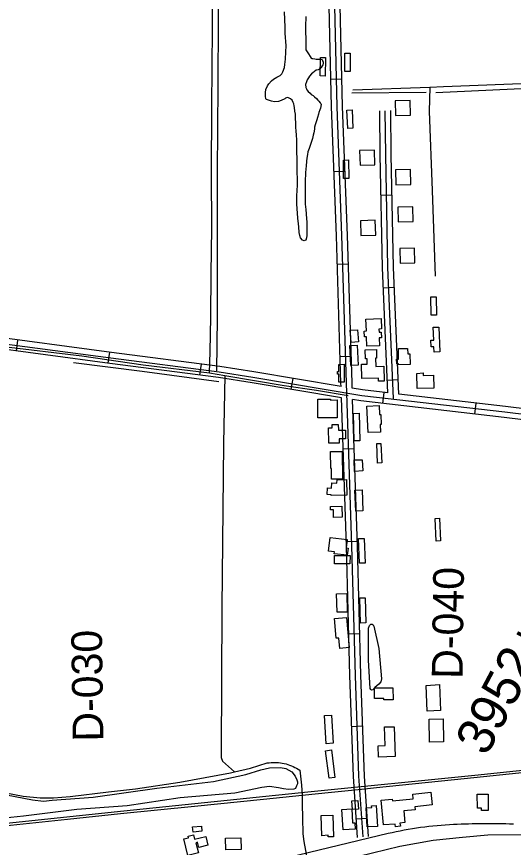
# Model space of a CAD drawing. Extents: x 3445503 to 3483459, y 540493 to 566012.
# Drawn here: x 3463733 to 3465075, y 553510 to 555755 of the extents above; entities that cross this region are included whole.
import ezdxf

# ---------------------------------------------------------------- set-up
doc = ezdxf.new("R2010")
doc.units = 0
for name, color, linetype in [('V-BLDG-OTLN', 7, 'Continuous'), ('V-DTCH-CNTR', 7, 'Continuous'), ('V-LEVE-TOET', 7, 'Continuous'), ('V-RAIL-TRAK', 7, 'Continuous'), ('V-RIVR-RANG-IDEN', 7, 'Continuous'), ('V-ROAD-CNTR', 7, 'Continuous'), ('V-SITE-VEGE', 7, 'Continuous'), ('V-SURV-IDEN', 7, 'Continuous'), ('V-TOPO-SHOR', 7, 'Continuous')]:
    doc.layers.add(name, color=color, linetype=linetype)

msp = doc.modelspace()

# ---------------------------------------------------------------- linework, layer by layer
at = {"layer": 'V-BLDG-OTLN'}
for points in [[(3464552.9878560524, 555594.4947846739), (3464554.1908536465, 555644.4806847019), (3464568.186825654, 555644.1436853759), (3464566.9838280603, 555594.1587853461)], [(3464634.2806934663, 555656.328661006), (3464634.32869337, 555606.3287610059), (3464620.3287213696, 555606.314761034), (3464620.280721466, 555656.3146610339)], [(3464756.330449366, 555527.7119182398), (3464757.1204477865, 555487.719998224), (3464797.1123678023, 555488.509996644), (3464796.322369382, 555528.5019166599)], [(3464639.6536827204, 555503.1039674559), (3464641.797678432, 555453.150067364), (3464627.8107064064, 555452.5500685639), (3464625.6657106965, 555502.5039686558)], [(3464701.0565599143, 555354.3532649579), (3464699.7665624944, 555394.3331849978), (3464659.7876424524, 555393.0441875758), (3464661.076639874, 555353.0642675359)], [(3464630.0230366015, 555367.5500286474), (3464630.818035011, 555317.5571286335), (3464616.8200630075, 555317.3341290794), (3464616.025064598, 555367.3280290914)], [(3464757.2384475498, 555340.6522923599), (3464758.0284459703, 555300.6603723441), (3464798.020365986, 555301.450370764), (3464797.230367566, 555341.4422907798)], [(3464763.505435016, 555240.275493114), (3464764.2954334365, 555200.2835730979), (3464804.287353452, 555201.073571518), (3464803.4973550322, 555241.065491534)], [(3464703.4295551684, 555164.68764429), (3464702.139557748, 555204.6675643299), (3464662.160637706, 555203.378566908), (3464663.449635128, 555163.398646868)], [(3464768.481425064, 555128.6677163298), (3464769.2714234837, 555088.675796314), (3464809.2633435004, 555089.465794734), (3464808.4733450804, 555129.4577147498)], [(3464866.7916951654, 554998.0646418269), (3464867.2241945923, 554948.0668042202), (3464853.224880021, 554947.9457069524), (3464852.792348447, 554997.9445440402)], [(3464679.497, 554864.221), (3464678.555, 554890.001), (3464672.757, 554889.7880000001), (3464672.19, 554905.269), (3464678.311, 554905.495), (3464677.144, 554937.378), (3464718.073, 554938.875), (3464719.095, 554910.95), (3464712.12, 554910.705), (3464712.429, 554901.935), (3464718.171, 554902.138), (3464718.7060000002, 554886.9890000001), (3464712.449, 554886.768), (3464713.207, 554865.317)], [(3464654.018, 554908.562), (3464656.715, 554875.639), (3464636.896, 554874.015), (3464634.543, 554907.422)], [(3464873.93, 554915.405), (3464876.396, 554848.904), (3464861.011, 554848.333), (3464860.468, 554862.943), (3464853.0100000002, 554862.667), (3464852.348, 554880.519), (3464860.04, 554880.804), (3464858.764, 554915.245)], [(3464653.727, 554867.3960000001), (3464656.053, 554812.806), (3464636.028, 554811.956), (3464633.896, 554866.279)], [(3464725.4990000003, 554810.183), (3464725.8370000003, 554769.446), (3464710.848, 554769.321), (3464710.778, 554777.642), (3464665.544, 554777.259), (3464665.222, 554815.383), (3464680.203, 554815.512), (3464680.0810000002, 554830.188), (3464675.382, 554830.147), (3464675.159, 554854.854), (3464705.65, 554855.1240000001), (3464705.855, 554831.977), (3464703.112, 554831.955), (3464703.323, 554809.6730000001)], [(3464795.823, 554843.975), (3464796.774, 554815.157), (3464765.019, 554814.115), (3464764.946, 554816.333), (3464760.17, 554816.177), (3464759.77, 554829.034), (3464765.1380000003, 554829.219), (3464764.737, 554857.95), (3464789.538, 554858.229), (3464790.1950000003, 554843.696)], [(3464618.231, 554815.536), (3464618.3680000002, 554767.441), (3464603.42, 554767.404), (3464603.365, 554788.8420000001), (3464600.106, 554788.836), (3464600.09, 554795.986), (3464603.553, 554795.9940000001), (3464603.723, 554815.061)], [(3464814.378, 554790.868), (3464831.68, 554791.888), (3464831.858, 554785.213), (3464859.2970000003, 554785.9450000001), (3464860.221, 554751.186), (3464815.472, 554749.9940000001)], [(3464599.303, 554718.938), (3464599.228, 554670.622), (3464547.333, 554670.72), (3464547.395, 554721.306), (3464581.091, 554721.248), (3464581.095, 554718.678)], [(3464682.7630000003, 554631.431), (3464679.739, 554702.274), (3464713.076, 554703.687), (3464714.096, 554679.975), (3464717.063, 554680.03), (3464718.044, 554652.509), (3464715.1920000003, 554652.435), (3464715.97, 554631.716)], [(3464643.397, 554682.017), (3464658.5640000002, 554682.902), (3464660.6720000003, 554608.803), (3464645.562, 554608.354)], [(3464604.268, 554602.1410000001), (3464576.755, 554601.844), (3464576.274, 554643.578), (3464585.733, 554643.674), (3464585.69, 554652.765), (3464602.386, 554652.837), (3464602.472, 554637.231), (3464622.149, 554637.264), (3464622.126, 554613.458), (3464604.235, 554613.566)], [(3464613.58, 554505.125), (3464583.5870000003, 554505.029), (3464583.6010000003, 554533.563), (3464581.795, 554533.432), (3464581.451, 554579.443), (3464612.929, 554579.658)], [(3464717.485, 554601.033), (3464719.589, 554548.807), (3464708.662, 554548.366), (3464706.541, 554601.252)], [(3464667.113, 554557.105), (3464668.501, 554526.981), (3464646.432, 554525.965), (3464645.017, 554556.685)], [(3464624.848, 554503.638), (3464625.841, 554461.609), (3464583.159, 554460.6730000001), (3464583.126, 554462.774), (3464572.294, 554463.102), (3464572.9390000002, 554481.126), (3464583.7060000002, 554480.9130000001), (3464584.791, 554495.071), (3464598.597, 554494.41), (3464599.129, 554502.9890000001)], [(3464647.413, 554474.903), (3464666.414, 554475.875), (3464668.563, 554419.203), (3464649.311, 554418.554)], [(3464581.295, 554431.36), (3464612.06, 554432.316), (3464612.98, 554402.26), (3464589.586, 554401.549), (3464588.971, 554422.214), (3464581.035, 554422.064)], [(3464866.944, 554337.263), (3464864.38, 554398.594), (3464875.857, 554399.073), (3464878.409, 554337.9940000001)], [(3464626.216, 554299.389), (3464591.097, 554303.403), (3464591.681, 554308.433), (3464576.108, 554310.325), (3464580.748, 554347.656), (3464626.075, 554342.008), (3464623.29, 554319.201), (3464629.327, 554318.235)], [(3464672.028, 554344.814), (3464674.819, 554278.292), (3464660.012, 554277.67), (3464657.196, 554344.449)], [(3464633.867, 554276.224), (3464592.043, 554276.316), (3464592.094, 554298.287), (3464634.2460000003, 554298.191)], [(3464625.024, 554196.078), (3464626.04, 554145.805), (3464598.8710000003, 554145.261), (3464597.876, 554195.049)], [(3464674.686, 554184.089), (3464676.617, 554116.478), (3464662.359, 554116.074), (3464660.4220000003, 554183.863)], [(3464624.35, 554130.63), (3464631.305, 554049.603), (3464606.045, 554047.434), (3464603.631, 554075.573), (3464596.926, 554074.998), (3464592.4590000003, 554127.867)], [(3464700.44, 553940.555), (3464750.083, 553940.7), (3464750.177, 553908.831), (3464725.0300000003, 553908.76), (3464725.022, 553911.795), (3464699.875, 553911.723)], [(3464875.361, 553949.955), (3464878.169, 553879.508), (3464842.512, 553878.074), (3464839.759, 553947.35)], [(3464584.382, 553867.214), (3464588.072, 553790.944), (3464569.171, 553790.029), (3464565.481, 553866.2980000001)], [(3464885.3910000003, 553856.765), (3464886.4390000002, 553794.7660000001), (3464848.795, 553794.143), (3464847.728, 553855.833)], [(3464753.211, 553835.781), (3464756.264, 553755.362), (3464711.012, 553753.642), (3464709.863, 553783.9130000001), (3464728.995, 553784.6410000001), (3464727.307, 553835.486)], [(3464583.575, 553773.161), (3464593.327, 553698.643), (3464577.504, 553696.5700000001), (3464567.8170000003, 553770.567)], [(3464724.457, 553570.833), (3464718.098, 553637.002), (3464748.326, 553639.984), (3464748.8200000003, 553635.104), (3464804.468, 553640.691), (3464803.477, 553653.984), (3464852.166, 553658.926), (3464855.916, 553624.737), (3464809.262, 553619.238), (3464809.934, 553610.921), (3464779.392, 553608.121), (3464782.239, 553577.151), (3464768.896, 553575.003), (3464769.994, 553566.782), (3464757.2430000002, 553565.089), (3464756.156, 553572.767)], [(3464640.603, 553611.824), (3464639.235, 553635.833), (3464655.4250000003, 553636.754), (3464656.801, 553612.602)], [(3465007.574, 553653.5480000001), (3465007.052, 553609.528), (3464989.103, 553609.735), (3464989.21, 553615.754), (3464978.196, 553615.517), (3464977.653, 553653.245)], [(3464612.048, 553612.393), (3464639.088, 553614.337), (3464640.89, 553575.898), (3464647.2120000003, 553576.189), (3464648.181, 553558.756), (3464615.132, 553556.919)], [(3464704.812, 553622.7220000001), (3464707.897, 553566.6), (3464680.146, 553565.111), (3464677.33, 553616.393), (3464692.514, 553617.2170000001), (3464692.186, 553622.326)], [(3464587.435, 553597.068), (3464589.2290000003, 553538.674), (3464574.705, 553538.235), (3464574.707, 553542.491), (3464558.075, 553541.178), (3464555.968, 553596.003)], [(3464208.6920000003, 553564.882), (3464232.31, 553567.213), (3464233.662, 553553.444), (3464210.38, 553551.158)], [(3464184.745, 553532.833), (3464197.918, 553535.931), (3464196.796, 553540.242), (3464211.0500000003, 553543.671), (3464214.001, 553531.561), (3464244.088, 553539.022), (3464249.788, 553515.754), (3464225.631, 553509.7660000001), (3464222.275, 553523.375), (3464217.751, 553522.261), (3464224.56, 553494.783), (3464195.927, 553487.691)], [(3464339.605, 553504.103), (3464298.188, 553503.335), (3464297.602, 553534.838), (3464338.595, 553535.598)]]:
    msp.add_lwpolyline(points, close=True, dxfattribs=at)
at = {"layer": 'V-DTCH-CNTR'}
for points in [[(3464254.058, 554791.97), (3464256.487, 554849.428), (3464257.832, 554943.561), (3464259.114, 555060.09), (3464260.376, 555183.435), (3464259.296, 555330.4670000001), (3464260.39, 555510.937), (3464262.688, 555723.8690000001), (3464263.458, 555903.366), (3464259.055, 555966.322)], [(3466325.821, 555717.35), (3466190.882, 555693.9130000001), (3465990.727, 555666.064), (3465767.855, 555637.827), (3465492.426, 555603.9180000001), (3465341.574, 555584.327), (3465142.988, 555574.984), (3464886.9590000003, 555564.822), (3464849.546, 555563.525), (3464641.312, 555556.312)], [(3464849.546, 555563.525), (3464847.787, 555499.263), (3464855.555, 555285.093), (3464864.345, 555053.727)], [(3462920.117, 555016.9180000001), (3462976.88, 555005.416), (3463146.526, 554968.634), (3463259.1, 554937.519), (3463342.157, 554913.127), (3463386.269, 554904.503), (3463527.014, 554884.8200000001), (3463697.585, 554863.275), (3463909.664, 554837.964), (3464075.38, 554814.137), (3464254.058, 554791.97)], [(3464254.058, 554791.97), (3464295.395, 554785.062), (3464456.109, 554758.2), (3464543.346, 554745.814), (3464628.666, 554731.134)], [(3464295.395, 554785.062), (3464292.126, 554601.145), (3464288.097, 554157.172), (3464285.818, 553765.746), (3464285.474, 553752.7980000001), (3464289.693, 553742.9130000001), (3464321.64, 553713.853)], [(3463633.77, 553670.247), (3463638.292, 553669.291), (3463679.794, 553661.31), (3463751.126, 553648.231), (3463796.8310000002, 553643.507), (3463832.803, 553643.935), (3463877.836, 553647.308), (3463981.174, 553660.2490000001), (3464054.0640000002, 553667.917), (3464173.911, 553686.414), (3464310.914, 553711.4450000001), (3464321.64, 553713.853), (3464364.998, 553723.594), (3464410.324, 553737.985)], [(3464410.324, 553737.985), (3464415.401, 553738.653), (3464420.503, 553739.107), (3464425.617, 553739.351), (3464430.739, 553739.384), (3464435.859, 553739.204), (3464440.964, 553738.81), (3464446.052, 553738.204), (3464451.108, 553737.389), (3464456.13, 553736.365), (3464461.102, 553735.134), (3464466.02, 553733.699), (3464470.873, 553732.058), (3464475.6550000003, 553730.221), (3464480.358, 553728.185), (3464484.972, 553725.955), (3464489.488, 553723.5380000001), (3464493.901, 553720.935), (3464498.202, 553718.15)], [(3464498.202, 553718.15), (3464502.857, 553678.304), (3464504.428, 553651.115), (3464504.4990000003, 553626.488), (3464505.257, 553589.2220000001), (3464506.678, 553546.45), (3464509.654, 553525.718), (3464516.753, 553487.085)]]:
    msp.add_lwpolyline(points, dxfattribs=at)
at = {"layer": 'V-LEVE-TOET'}
msp.add_lwpolyline([(3464658.224, 553486.218), (3464768.751, 553512.568), (3464858.486, 553529.095), (3464937.8340000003, 553537.787), (3465006.128, 553543.843), (3465102.417, 553544.775), (3465298.912, 553540.795), (3465626.836, 553534.6), (3465949.56, 553526.439), (3466237.791, 553522.079), (3466528.632, 553515.775), (3466792.791, 553511.343), (3466823.378, 553508.181)], dxfattribs=at)
at = {"layer": 'V-RAIL-TRAK'}
msp.add_lwpolyline([(3463647.612, 553562.609), (3463870.883, 553585.628), (3464013.461, 553600.957), (3464213.722, 553621.317), (3464400.375, 553640.017), (3464504.428, 553651.115), (3464583.788, 553659.031), (3464665.257, 553667.505), (3464705.627, 553671.706), (3464942.184, 553695.737), (3465116.522, 553713.751), (3465289.563, 553731.438), (3465488.203, 553752.765), (3465635.966, 553768.109), (3465761.699, 553780.796), (3465957.099, 553800.818)], dxfattribs=at)
at = {"layer": 'V-ROAD-CNTR'}
for p, q in [((3464582.247797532, 555586.1208014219), (3464612.239737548, 555586.8048000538)), ((3464590.584780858, 555336.040301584), (3464620.5627209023, 555337.1752993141)), ((3464717.6675266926, 555272.693428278), (3464747.661466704, 555273.256427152)), ((3464599.5217629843, 555086.3038010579), (3464629.507703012, 555087.2357991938)), ((3464723.664514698, 555022.4169288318), (3464753.636454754, 555023.7019262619)), ((3463732.8304963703, 554851.1762713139), (3463736.7704884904, 554880.916211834)), ((3463980.666000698, 554818.3503369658), (3463984.60499282, 554848.0902774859)), ((3464607.2917474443, 554836.424300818), (3464637.2766874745, 554837.3572989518)), ((3464228.6195047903, 554786.1334013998), (3464232.4834970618, 554815.8833418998)), ((3464475.0690118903, 554747.671478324), (3464480.0090020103, 554777.2624191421)), ((3464734.377493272, 554772.6464283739), (3464764.350433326, 554773.932425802)), ((3464722.829516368, 554709.3835549), (3464726.2635095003, 554739.1864952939)), ((3464971.185019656, 554680.76361214), (3464974.620012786, 554710.5665525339)), ((3464615.5147309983, 554586.522800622), (3464645.497671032, 554587.5307986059)), ((3464623.91871419, 554336.66430034), (3464653.9016542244, 554337.6722983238)), ((3464630.5467009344, 554086.8647999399), (3464660.536640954, 554087.6497983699)), ((3464638.335685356, 553836.853299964), (3464668.316625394, 553837.9102978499)), ((3464650.877660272, 553586.7138002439), (3464680.80860041, 553588.742796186))]:
    msp.add_line(p, q, dxfattribs=at)
for points in [[(3464640.014681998, 554750.5524725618), (3464639.513683, 554765.420442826), (3464627.134707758, 555163.5386465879), (3464613.949734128, 555511.922949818), (3464603.285755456, 555979.0970154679), (3464587.05378792, 556403.0031676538), (3464588.709784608, 556520.0239336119), (3464579.83880235, 556696.1285814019), (3464566.4518291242, 557015.8579419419), (3464565.69383064, 557133.317707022), (3464478.852004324, 557129.8217140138)], [(3464609.827742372, 554755.5914624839), (3464609.5297429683, 554764.4504447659), (3464597.152767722, 555162.5046486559), (3464583.961794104, 555511.012951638), (3464573.299815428, 555978.1810172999), (3464557.045847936, 556402.641168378), (3464558.6998446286, 556519.481934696), (3464549.870862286, 556694.7465841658), (3464536.4558891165, 557015.1339433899), (3464535.8938902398, 557102.09376947), (3464480.058001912, 557099.8457739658)], [(3464669.224623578, 553537.842897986), (3464658.105645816, 553701.8675699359), (3464648.490665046, 553974.4790247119), (3464639.3396833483, 554324.4073248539), (3464624.521712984, 554764.935443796), (3464612.14373774, 555163.0216476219), (3464598.9557641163, 555511.4679507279), (3464588.2927854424, 555978.6390163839)], [(3464735.860490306, 554738.081497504), (3464721.3525193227, 555076.305821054), (3464715.6185307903, 555381.8822099), (3464714.1345337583, 555500.500972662)], [(3464751.506459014, 554723.335526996), (3464736.346489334, 555076.7678201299), (3464730.6165007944, 555382.11720943), (3464729.13350376, 555500.688972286)], [(3464766.036429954, 554734.6035044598), (3464751.340459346, 555077.229819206), (3464745.614470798, 555382.3522089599), (3464744.132473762, 555500.87697191)], [(3464609.827742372, 554755.5914624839), (3464374.047213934, 554794.950383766), (3464282.6873966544, 554809.36335494), (3463989.2509835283, 554847.4752787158), (3463639.962682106, 554893.7381861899), (3463418.709124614, 554912.3141490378), (3463332.4262971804, 554940.2690931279), (3463277.285407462, 554958.12305742), (3463208.6945446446, 554982.512008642), (3463157.18164767, 554995.07298352), (3462918.576124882, 555036.0539015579), (3462796.2523695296, 555038.326897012)], [(3464610.856740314, 554725.0045236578), (3464369.23922355, 554765.3384429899), (3464278.417405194, 554779.665414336), (3463985.348991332, 554817.729338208), (3463636.736688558, 554863.904245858), (3463412.7531365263, 554882.7082082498), (3463323.182315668, 554911.7291502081), (3463267.6374267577, 554929.71311424), (3463200.0925618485, 554953.730066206), (3463151.08165987, 554965.6810423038), (3462915.7421305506, 555006.1019614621), (3462795.694370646, 555008.332957)], [(3463638.3496853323, 554878.8212160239), (3463987.29998743, 554832.6023084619), (3464280.552400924, 554794.5143846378), (3464371.643218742, 554780.144413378), (3464665.5096310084, 554731.0885114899), (3465052.138857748, 554686.5336006), (3465440.0010820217, 554638.8926958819), (3465471.7460185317, 554638.096697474), (3465512.085937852, 554636.930699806), (3465552.17185768, 554636.9556997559), (3465650.6256607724, 554644.390684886), (3466146.099669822, 554711.1975512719), (3466532.7968964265, 554756.6004604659), (3466917.007128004, 554810.084353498), (3467040.951880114, 554820.7023322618), (3467493.343975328, 554879.0952154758), (3467696.094569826, 554903.5841664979), (3467752.335457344, 554909.2991550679)], [(3466439.5670828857, 554760.757452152), (3466144.2226735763, 554726.0805215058), (3465649.057663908, 554659.314655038), (3465551.60185882, 554651.9556697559), (3465512.297937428, 554651.930669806), (3465472.151017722, 554653.0916674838), (3465441.106079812, 554653.869665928), (3465053.9118542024, 554701.4285708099), (3464766.036429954, 554734.6035044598)], [(3464735.860490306, 554738.081497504), (3464667.604626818, 554745.9464817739), (3464640.014681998, 554750.5524725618)], [(3464654.2586535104, 553536.8289000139), (3464643.1236757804, 553701.0955714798), (3464633.497695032, 553974.019025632), (3464624.3467133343, 554323.9593257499), (3464610.856740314, 554725.0045236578)], [(3466444.176073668, 554731.092511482), (3466147.976666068, 554696.314581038), (3465652.193657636, 554629.4667147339), (3465552.7418565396, 554621.9557297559), (3465511.8739382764, 554621.930729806), (3465471.3410193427, 554623.101727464), (3465438.8960842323, 554623.9157258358), (3465050.365861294, 554671.6386303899), (3464663.414635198, 554716.2305412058), (3464641.042679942, 554719.965533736)], [(3464684.190593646, 553538.856895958), (3464673.0876158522, 553702.6395683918), (3464663.4836350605, 553974.939023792), (3464654.3326533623, 554324.855323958), (3464641.042679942, 554719.965533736)], [(3462633.1446957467, 553462.7350482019), (3463482.4409971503, 553551.6268704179), (3464022.895916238, 553608.7357561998), (3464520.2349215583, 553660.05565356), (3464971.126019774, 553704.8295640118), (3465529.4559031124, 553763.5944464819), (3465882.8481963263, 553800.9443717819), (3466138.079685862, 553826.5673205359), (3466333.4622950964, 553848.816276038), (3466574.421813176, 553870.9202318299), (3467118.44872512, 553928.552116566), (3467570.959820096, 553977.4020188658), (3467901.9681580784, 554011.130951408), (3468263.5194349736, 554044.7658841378), (3468297.7413665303, 554048.5228766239)], [(3464736.6394887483, 553546.798880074), (3464174.493613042, 553411.6311504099), (3463811.714338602, 553323.578326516), (3463601.09575984, 553279.424414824)]]:
    msp.add_lwpolyline(points, dxfattribs=at)
for centre, radius, start, end in [((3464963.076483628, 552568.1018587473), 1004.5504328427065, 92.80835923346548, 103.02706756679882), ((3465009.6029051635, 551301.8366162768), 2271.627840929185, 88.34062572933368, 92.41562850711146)]:
    msp.add_arc(centre, radius, start, end, dxfattribs=at)
at = {"layer": 'V-SITE-VEGE'}
for points in [[(3464440.731, 555525.934), (3464429.997, 555524.955), (3464421.785, 555526.512), (3464411.041, 555529.637), (3464407.881, 555530.89), (3464406.607, 555534.044), (3464405.644, 555539.408), (3464405.298, 555550.1410000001), (3464406.222, 555557.721), (3464410.613, 555567.838), (3464415.018, 555573.218), (3464422.254, 555581.765), (3464427.609, 555585.885), (3464436.117, 555591.593), (3464441.478, 555593.819), (3464445.261, 555596.039), (3464449.668, 555600.473), (3464452.495, 555605.534), (3464456.566, 555617.228), (3464458.1180000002, 555625.756), (3464459.654, 555640.284), (3464460.861, 555659.5480000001), (3464461.129, 555675.964), (3464458.819, 555710.057), (3464458.454, 555726.159), (3464456.754, 555768.145)], [(3464514.5670000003, 555755.685), (3464514.602, 555744.003), (3464513.984, 555739.581), (3464514.193, 555668.542), (3464514.8340000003, 555665.389), (3464521.4960000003, 555654.358), (3464526.569, 555646.795), (3464529.106, 555642.6950000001), (3464531.007, 555641.757), (3464533.532, 555641.447), (3464538.9020000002, 555640.5160000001), (3464542.691, 555640.21), (3464555.003, 555640.247), (3464559.111, 555639), (3464560.066, 555636.7880000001), (3464561.028, 555631.742)], [(3464561.028, 555631.742), (3464561.036, 555628.584), (3464560.416, 555625.108), (3464559.161, 555622.264), (3464556.3340000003, 555617.519), (3464555.077, 555615.618), (3464550.981, 555612.452), (3464548.142, 555611.495), (3464542.781, 555609.902), (3464533.327, 555602.929), (3464529.864, 555600.076), (3464524.83, 555594.063), (3464521.684, 555589.948), (3464518.2290000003, 555583.9400000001), (3464516.036, 555578.879), (3464514.162, 555571.615), (3464514.184, 555563.7220000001), (3464516.089, 555559.6240000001), (3464517.676, 555557.103), (3464520.529, 555553.007), (3464525.913, 555547.653), (3464529.393, 555544.507), (3464534.4560000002, 555541.368), (3464538.255, 555538.218), (3464543.3170000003, 555533.813), (3464547.438, 555529.088), (3464549.656, 555526.254), (3464553.772, 555522.16), (3464555.042, 555519.956), (3464555.9960000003, 555517.746), (3464554.131, 555507.637), (3464552.2490000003, 555503.214), (3464549.744, 555496.261), (3464548.497, 555490.889), (3464545.994, 555482.672), (3464544.433, 555476.354), (3464539.424, 555462.446), (3464538.179, 555456.128), (3464537.88, 555450.76), (3464536.012, 555440.969), (3464534.1380000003, 555434.331), (3464532.5840000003, 555425.803), (3464531.021, 555420.431), (3464528.83, 555414.742), (3464523.507, 555398.9400000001), (3464520.38, 555389.142), (3464519.134, 555382.509), (3464516.953, 555372.715), (3464516.032, 555364.187), (3464515.122, 555351.24), (3464514.83, 555343.662), (3464513.597, 555332.922), (3464513.6210000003, 555325.3470000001), (3464513.015, 555316.504), (3464513.1580000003, 555266.936), (3464512.878, 555255.567), (3464513.216, 555247.676), (3464514.203, 555234.102), (3464516.484, 555209.799), (3464517.146, 555199.698), (3464517.504, 555184.5430000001), (3464517.5330000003, 555175.386), (3464517.252, 555163.074), (3464516.64, 555157.073), (3464514.447, 555151.066), (3464512.241, 555149.483), (3464509.718, 555148.8420000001), (3464505.923, 555150.726), (3464500.537, 555157.341), (3464497.995, 555163.0160000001), (3464497.022, 555171.223), (3464496.031, 555186.689), (3464494.745, 555194.895), (3464492.803, 555210.044), (3464490.481, 555248.555), (3464490.417, 555270.3420000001), (3464491.9080000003, 555299.708), (3464491.853, 555318.9670000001), (3464491.183, 555331.911), (3464490.815, 555350.2220000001), (3464490.639, 555410.21), (3464489.969, 555423.469), (3464488.994, 555432.936), (3464488.316, 555448.405), (3464487.671, 555453.453), (3464487.308, 555468.926), (3464486.649, 555478.711), (3464486.2970000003, 555491.339), (3464485.326, 555499.228), (3464484.349, 555509.014), (3464483.389, 555514.062), (3464481.793, 555519.426), (3464480.521, 555522.895), (3464477.347, 555528.883), (3464473.548, 555532.346), (3464468.17, 555535.488), (3464465.325, 555536.426), (3464459.964, 555534.515), (3464457.4450000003, 555532.615), (3464447.669, 555528.164), (3464440.731, 555525.934)], [(3463705.781, 553651.801), (3463776.167, 553638.3910000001), (3463806.004, 553634.59), (3463829.665, 553636.926), (3463940.187, 553645.68), (3464111.613, 553669.848), (3464265.225, 553688.129), (3464352.378, 553706.866), (3464392.865, 553719.629), (3464416.1920000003, 553724.882), (3464446.0130000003, 553725.941), (3464460.611, 553723.0650000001), (3464476.524, 553714.359), (3464485.957, 553702.393), (3464490.526, 553692.679), (3464492.164, 553686.525), (3464491.853, 553681.6630000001), (3464489.6, 553676.144), (3464487.028, 553669.004), (3464482.168, 553667.368), (3464467.9080000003, 553666.354), (3464454.289, 553667.612), (3464440.989, 553670.4890000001), (3464416.665, 553673.985), (3464395.597, 553671.652), (3464322.377, 553656.526), (3464174.907, 553643.775), (3464032.001, 553621.96), (3463896.194, 553612.484), (3463751.984, 553593.906), (3463631.423, 553581.233)]]:
    msp.add_lwpolyline(points, dxfattribs=at)
msp.add_lwpolyline([(3464688.1010000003, 553939.228), (3464684.302, 554015.284), (3464684.373, 554102.085), (3464686.626, 554109.242), (3464689.8680000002, 554112.828), (3464693.767, 554112.843), (3464696.698, 554111.223), (3464698.66, 554107.651), (3464711.515, 554047.225), (3464718.909, 553964.998), (3464717.631, 553957.193), (3464712.1240000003, 553950.674), (3464700.649, 553941.468), (3464695.262, 553935.67), (3464692.014, 553935.011), (3464690.06, 553935.98)], close=True, dxfattribs=at)
at = {"layer": 'V-TOPO-SHOR'}
msp.add_line((3464839.866, 555549.853), (3464638.707, 555547.962), dxfattribs=at)
for points in [[(3464274.556, 554797.368), (3464275.758, 554940.839), (3464275.525, 555131.0430000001), (3464276.227, 555334.557), (3464278.1380000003, 555568.586), (3464278.2630000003, 555746.782), (3464277.376, 555939.257)], [(3466443.396, 554752.167), (3466417.4050000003, 554957.487), (3466388.119, 555176.4720000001), (3466360.792, 555392.531), (3466333.771, 555616.73), (3466322.159, 555691.564), (3466320.85, 555693.188), (3466317.2660000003, 555694.478), (3466164.014, 555672.872), (3465949.906, 555645.877), (3465734.168, 555619.855), (3465472.222, 555588.49), (3465348.253, 555571.525), (3465268.205, 555561.852), (3465116.194, 555560.429), (3464865.91, 555548.954)], [(3463887.017, 554820.517), (3464072.844, 554797.03), (3464279.469, 554768.731)]]:
    msp.add_lwpolyline(points, dxfattribs=at)

# ---------------------------------------------------------------- texts
at = {"layer": 'V-RIVR-RANG-IDEN'}
for s, rotation, p in [('D-040', 89.20007405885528, (3464937.780971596, 553964.7207369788)), ('D-030', 90.80949372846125, (3463967.879, 553796.019))]:
    msp.add_text(s, height=82.999998, rotation=rotation, dxfattribs=at).set_placement(p)
at = {"layer": 'V-SURV-IDEN'}
msp.add_text('3952+83.4', height=100, rotation=62.10387230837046, dxfattribs=at).set_placement((3465002.5355064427, 553753.299557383))

doc.saveas('drawing.dxf')
